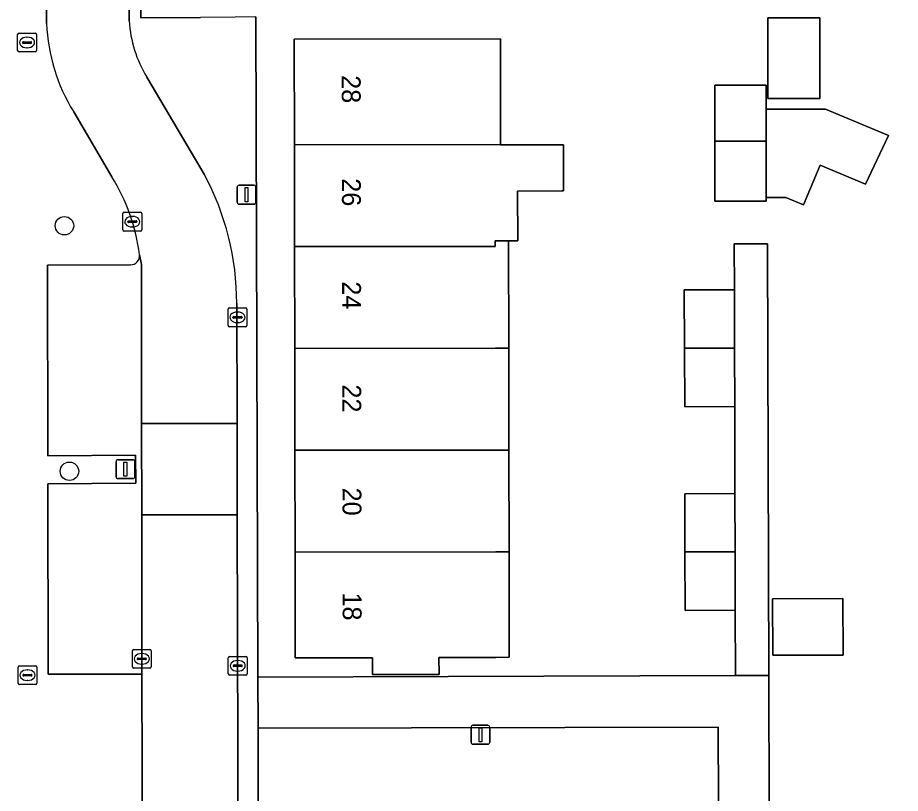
# Model space of a CAD drawing. Extents: x 160455 to 162082, y 388339 to 389736.
# Drawn here: x 160945.33 to 160992.11, y 388549.23 to 388590.36 of the extents above; entities that cross this region are included whole.
import ezdxf

# ---------------------------------------------------------------- set-up
doc = ezdxf.new("R2010")
doc.units = 0
for name, color, linetype in [('IMGEO_Boom', 7, 'Continuous'), ('IMGEO_Brandkraan', 7, 'Continuous'), ('IMGEO_Erf', 7, 'Continuous'), ('IMGEO_Groenvoorziening', 7, 'Continuous'), ('IMGEO_Kolk', 7, 'Continuous'), ('IMGEO_Lichtmast', 7, 'Continuous'), ('IMGEO_Muur', 7, 'Continuous'), ('IMGEO_Pand', 7, 'Continuous'), ('IMGEO_Pand_nummerreeks', 7, 'Continuous'), ('IMGEO_Parkeervlak_open', 7, 'Continuous'), ('IMGEO_Rijbaan_lokaal_open', 7, 'Continuous'), ('IMGEO_Voetpad_open', 7, 'Continuous')]:
    doc.layers.add(name, color=color, linetype=linetype)

msp = doc.modelspace()

# ---------------------------------------------------------------- linework, layer by layer
at = {"layer": 'IMGEO_Boom'}
for centre in [(160947.807, 388579.324), (160948.073, 388566.305)]:
    msp.add_circle(centre, 0.489, dxfattribs=at)
at = {"layer": 'IMGEO_Brandkraan'}
for p, q in [((160945.326, 388588.611), (160945.326, 388589.463)), ((160945.401, 388589.537), (160946.253, 388589.537)), ((160945.814, 388589.317), (160945.839, 388589.317)), ((160946.327, 388589.463), (160946.327, 388588.611)), ((160945.585, 388589.031), (160945.585, 388589.043)), ((160946.023, 388588.994), (160945.625, 388588.994)), ((160945.628, 388589.08), (160946.026, 388589.08)), ((160945.837, 388588.757), (160945.812, 388588.757)), ((160946.069, 388589.043), (160946.069, 388589.031)), ((160946.253, 388588.537), (160945.401, 388588.537)), ((160945.347, 388555.071), (160945.347, 388555.923)), ((160945.422, 388555.997), (160946.274, 388555.997)), ((160945.649, 388555.54), (160946.047, 388555.54)), ((160945.835, 388555.777), (160945.86, 388555.777)), ((160946.348, 388555.923), (160946.348, 388555.071)), ((160945.606, 388555.491), (160945.606, 388555.503)), ((160946.044, 388555.454), (160945.646, 388555.454)), ((160945.858, 388555.217), (160945.833, 388555.217)), ((160946.09, 388555.503), (160946.09, 388555.491)), ((160946.274, 388554.997), (160945.422, 388554.997))]:
    msp.add_line(p, q, dxfattribs=at)
for points in [[(160945.326, 388588.611), (160945.326, 388589.463)], [(160945.401, 388589.537), (160946.253, 388589.537)], [(160946.327, 388589.463), (160946.327, 388588.611)], [(160946.253, 388588.537), (160945.401, 388588.537)], [(160945.347, 388555.071), (160945.347, 388555.923)], [(160945.422, 388555.997), (160946.274, 388555.997)], [(160946.348, 388555.923), (160946.348, 388555.071)], [(160946.274, 388554.997), (160945.422, 388554.997)]]:
    msp.add_lwpolyline(points, dxfattribs=at)
for centre, radius, start, end in [((160945.403, 388589.461), 0.0765, 91.552, 178.448), ((160945.403, 388589.461), 0.0765, 91.552, 178.448), ((160946.251, 388589.461), 0.0765, 1.552, 88.448), ((160946.251, 388589.461), 0.0765, 1.552, 88.448), ((160945.625, 388589.04), 0.0403, 85.8775, 175.7526), ((160945.622, 388589.03), 0.0366, 178.938, 274.7102), ((160946.026, 388589.037), 0.043, 264.8664, 352.4533), ((160946.03, 388589.042), 0.0386, 1.7309, 96.639), ((160945.403, 388588.613), 0.0765, 181.552, 268.448), ((160945.403, 388588.613), 0.0765, 181.552, 268.448), ((160946.251, 388588.613), 0.0765, 271.552, 358.448), ((160946.251, 388588.613), 0.0765, 271.552, 358.448), ((160945.424, 388555.921), 0.0765, 91.552, 178.448), ((160945.424, 388555.921), 0.0765, 91.552, 178.448), ((160945.646, 388555.5), 0.0403, 85.8775, 175.7526), ((160946.051, 388555.502), 0.0386, 1.7309, 96.639), ((160946.272, 388555.921), 0.0765, 1.552, 88.448), ((160946.272, 388555.921), 0.0765, 1.552, 88.448), ((160945.424, 388555.073), 0.0765, 181.552, 268.448), ((160945.424, 388555.073), 0.0765, 181.552, 268.448), ((160945.643, 388555.49), 0.0366, 178.938, 274.7102), ((160946.047, 388555.497), 0.043, 264.8664, 352.4533), ((160946.272, 388555.073), 0.0765, 271.552, 358.448), ((160946.272, 388555.073), 0.0765, 271.552, 358.448)]:
    msp.add_arc(centre, radius, start, end, dxfattribs=at)
for centre, major_axis, ratio, start_param, end_param in [((160945.813, 388589.037), (-0.387, 0.002), 0.722429, 4.712389, 7.853982), ((160945.838, 388589.037), (-0.39, 0.002), 0.717154, 1.570796, 4.712389), ((160945.834, 388555.497), (-0.387, 0.002), 0.722429, 4.712389, 7.853982), ((160945.859, 388555.497), (-0.39, 0.002), 0.717154, 1.570796, 4.712389)]:
    msp.add_ellipse(centre, major_axis=major_axis, ratio=ratio, start_param=start_param, end_param=end_param, dxfattribs=at)
at = {"layer": 'IMGEO_Erf'}
for points in [[(160951.847, 388593.555), (160951.861, 388590.348), (160955.023, 388590.37)], [(160957.949, 388590.391), (160958.051, 388555.395), (160968.14, 388555.428), (160983.369, 388555.475), (160983.358, 388558.935), (160980.699, 388558.927), (160980.689, 388562.038), (160980.68, 388565.117), (160983.338, 388565.126), (160983.338, 388569.735), (160980.679, 388569.727), (160980.669, 388572.838), (160980.66, 388575.917), (160983.318, 388575.926), (160983.31, 388578.36), (160985.07, 388578.366), (160985.147, 388555.481), (160985.162, 388548.37)]]:
    msp.add_lwpolyline(points, dxfattribs=at)
for points in [[(160987.85, 388586.062), (160985.087, 388586.062), (160985.087, 388590.342), (160987.85, 388590.342)], [(160970.921, 388583.612), (160974.072, 388583.618), (160974.253, 388583.618), (160974.256, 388581.167), (160974.175, 388581.167), (160971.823, 388581.163), (160971.83, 388578.532), (160971.583, 388578.531), (160971.342, 388578.53), (160971.352, 388572.83), (160971.362, 388567.433), (160971.372, 388562.031), (160971.382, 388556.442), (160970.676, 388556.44), (160968.137, 388556.434), (160967.655, 388556.433), (160967.667, 388555.533), (160964.137, 388555.524), (160964.125, 388556.423), (160960.039, 388556.412), (160960.029, 388562.021), (160960.02, 388567.422), (160960.01, 388572.822), (160960, 388578.222), (160959.991, 388583.627), (160959.981, 388589.211), (160970.911, 388589.231)], [(160985.003, 388585.504), (160988.141, 388585.504), (160991.484, 388584.1), (160990.267, 388581.523), (160987.857, 388582.534), (160986.975, 388580.433), (160986.04, 388580.825), (160985.003, 388580.825), (160985.003, 388580.627), (160982.273, 388580.627), (160982.273, 388583.801), (160982.273, 388586.785), (160985.003, 388586.785)], [(160989.066, 388559.56), (160989.073, 388556.559), (160985.348, 388556.551), (160985.341, 388559.551)]]:
    msp.add_lwpolyline(points, close=True, dxfattribs=at)
at = {"layer": 'IMGEO_Groenvoorziening'}
msp.add_lwpolyline([(160958.098, 388540.667), (160982.501, 388540.818), (160982.455, 388552.733), (160958.068, 388552.684)], close=True, dxfattribs=at)
at = {"layer": 'IMGEO_Kolk'}
for p, q in [((160950.903, 388579.112), (160950.903, 388579.964)), ((160950.978, 388580.038), (160951.83, 388580.038)), ((160951.904, 388579.964), (160951.904, 388579.112)), ((160951.162, 388579.532), (160951.162, 388579.544)), ((160951.6, 388579.495), (160951.202, 388579.495)), ((160951.205, 388579.581), (160951.603, 388579.581)), ((160951.391, 388579.818), (160951.416, 388579.818)), ((160951.646, 388579.544), (160951.646, 388579.532)), ((160951.83, 388579.038), (160950.978, 388579.038)), ((160951.414, 388579.258), (160951.389, 388579.258)), ((160956.477, 388574.042), (160956.477, 388574.894)), ((160956.552, 388574.968), (160957.404, 388574.968)), ((160956.965, 388574.748), (160956.99, 388574.748)), ((160957.478, 388574.894), (160957.478, 388574.042)), ((160956.736, 388574.462), (160956.736, 388574.474)), ((160957.174, 388574.425), (160956.776, 388574.425)), ((160956.779, 388574.511), (160957.177, 388574.511)), ((160957.22, 388574.474), (160957.22, 388574.462)), ((160957.404, 388573.968), (160956.552, 388573.968)), ((160956.988, 388574.188), (160956.963, 388574.188)), ((160951.406, 388555.936), (160951.406, 388556.788)), ((160951.481, 388556.862), (160952.333, 388556.862)), ((160951.894, 388556.642), (160951.919, 388556.642)), ((160952.407, 388556.788), (160952.407, 388555.936)), ((160956.566, 388556.493), (160957.418, 388556.493)), ((160951.665, 388556.356), (160951.665, 388556.368)), ((160952.103, 388556.319), (160951.705, 388556.319)), ((160951.708, 388556.405), (160952.106, 388556.405)), ((160951.917, 388556.082), (160951.892, 388556.082)), ((160952.149, 388556.368), (160952.149, 388556.356)), ((160956.491, 388555.567), (160956.491, 388556.419)), ((160956.793, 388556.036), (160957.191, 388556.036)), ((160956.979, 388556.273), (160957.004, 388556.273)), ((160957.492, 388556.419), (160957.492, 388555.567)), ((160952.333, 388555.862), (160951.481, 388555.862)), ((160956.75, 388555.987), (160956.75, 388555.999)), ((160957.188, 388555.95), (160956.79, 388555.95)), ((160957.002, 388555.713), (160956.977, 388555.713)), ((160957.234, 388555.999), (160957.234, 388555.987)), ((160957.418, 388555.493), (160956.566, 388555.493))]:
    msp.add_line(p, q, dxfattribs=at)
for points in [[(160950.903, 388579.112), (160950.903, 388579.964)], [(160950.978, 388580.038), (160951.83, 388580.038)], [(160951.904, 388579.964), (160951.904, 388579.112)], [(160951.83, 388579.038), (160950.978, 388579.038)], [(160956.477, 388574.042), (160956.477, 388574.894)], [(160956.552, 388574.968), (160957.404, 388574.968)], [(160957.478, 388574.894), (160957.478, 388574.042)], [(160957.404, 388573.968), (160956.552, 388573.968)], [(160951.406, 388555.936), (160951.406, 388556.788)], [(160951.481, 388556.862), (160952.333, 388556.862)], [(160952.407, 388556.788), (160952.407, 388555.936)], [(160956.566, 388556.493), (160957.418, 388556.493)], [(160956.491, 388555.567), (160956.491, 388556.419)], [(160957.492, 388556.419), (160957.492, 388555.567)], [(160952.333, 388555.862), (160951.481, 388555.862)], [(160957.418, 388555.493), (160956.566, 388555.493)]]:
    msp.add_lwpolyline(points, dxfattribs=at)
for centre, radius, start, end in [((160950.98, 388579.962), 0.0765, 91.552, 178.448), ((160950.98, 388579.962), 0.0765, 91.552, 178.448), ((160951.828, 388579.962), 0.0765, 1.552, 88.448), ((160951.828, 388579.962), 0.0765, 1.552, 88.448), ((160951.202, 388579.541), 0.0403, 85.8775, 175.7526), ((160951.199, 388579.531), 0.0366, 178.938, 274.7102), ((160951.603, 388579.538), 0.043, 264.8664, 352.4533), ((160951.607, 388579.543), 0.0386, 1.7309, 96.639), ((160950.98, 388579.114), 0.0765, 181.552, 268.448), ((160950.98, 388579.114), 0.0765, 181.552, 268.448), ((160951.828, 388579.114), 0.0765, 271.552, 358.448), ((160951.828, 388579.114), 0.0765, 271.552, 358.448), ((160956.554, 388574.892), 0.0765, 91.552, 178.448), ((160956.554, 388574.892), 0.0765, 91.552, 178.448), ((160957.402, 388574.892), 0.0765, 1.552, 88.448), ((160957.402, 388574.892), 0.0765, 1.552, 88.448), ((160956.776, 388574.471), 0.0403, 85.8775, 175.7526), ((160956.773, 388574.461), 0.0366, 178.938, 274.7102), ((160957.177, 388574.468), 0.043, 264.8664, 352.4533), ((160957.181, 388574.473), 0.0386, 1.7309, 96.639), ((160956.554, 388574.044), 0.0765, 181.552, 268.448), ((160956.554, 388574.044), 0.0765, 181.552, 268.448), ((160957.402, 388574.044), 0.0765, 271.552, 358.448), ((160957.402, 388574.044), 0.0765, 271.552, 358.448), ((160951.483, 388556.786), 0.0765, 91.552, 178.448), ((160951.483, 388556.786), 0.0765, 91.552, 178.448), ((160952.331, 388556.786), 0.0765, 1.552, 88.448), ((160952.331, 388556.786), 0.0765, 1.552, 88.448), ((160956.568, 388556.417), 0.0765, 91.552, 178.448), ((160956.568, 388556.417), 0.0765, 91.552, 178.448), ((160957.416, 388556.417), 0.0765, 1.552, 88.448), ((160957.416, 388556.417), 0.0765, 1.552, 88.448), ((160951.705, 388556.365), 0.0403, 85.8775, 175.7526), ((160951.702, 388556.355), 0.0366, 178.938, 274.7102), ((160952.106, 388556.362), 0.043, 264.8664, 352.4533), ((160952.11, 388556.367), 0.0386, 1.7309, 96.639), ((160956.79, 388555.996), 0.0403, 85.8775, 175.7526), ((160957.195, 388555.998), 0.0386, 1.7309, 96.639), ((160951.483, 388555.938), 0.0765, 181.552, 268.448), ((160951.483, 388555.938), 0.0765, 181.552, 268.448), ((160952.331, 388555.938), 0.0765, 271.552, 358.448), ((160952.331, 388555.938), 0.0765, 271.552, 358.448), ((160956.568, 388555.569), 0.0765, 181.552, 268.448), ((160956.568, 388555.569), 0.0765, 181.552, 268.448), ((160956.787, 388555.986), 0.0366, 178.938, 274.7102), ((160957.191, 388555.993), 0.043, 264.8664, 352.4533), ((160957.416, 388555.569), 0.0765, 271.552, 358.448), ((160957.416, 388555.569), 0.0765, 271.552, 358.448)]:
    msp.add_arc(centre, radius, start, end, dxfattribs=at)
for centre, major_axis, ratio, start_param, end_param in [((160951.39, 388579.538), (-0.387, 0.002), 0.722429, 4.712389, 7.853982), ((160951.415, 388579.538), (-0.39, 0.002), 0.717154, 1.570796, 4.712389), ((160956.964, 388574.468), (-0.387, 0.002), 0.722429, 4.712389, 7.853982), ((160956.989, 388574.468), (-0.39, 0.002), 0.717154, 1.570796, 4.712389), ((160951.893, 388556.362), (-0.387, 0.002), 0.722429, 4.712389, 7.853982), ((160951.918, 388556.362), (-0.39, 0.002), 0.717154, 1.570796, 4.712389), ((160956.978, 388555.993), (-0.387, 0.002), 0.722429, 4.712389, 7.853982), ((160957.003, 388555.993), (-0.39, 0.002), 0.717154, 1.570796, 4.712389)]:
    msp.add_ellipse(centre, major_axis=major_axis, ratio=ratio, start_param=start_param, end_param=end_param, dxfattribs=at)
at = {"layer": 'IMGEO_Lichtmast'}
for p, q in [((160956.961, 388580.568), (160956.961, 388581.368)), ((160956.961, 388581.368), (160956.961, 388580.568)), ((160957.061, 388581.468), (160957.851, 388581.468)), ((160957.851, 388581.468), (160957.061, 388581.468)), ((160957.951, 388581.368), (160957.951, 388580.568)), ((160957.951, 388580.568), (160957.951, 388581.368)), ((160957.851, 388580.468), (160957.061, 388580.468)), ((160957.061, 388580.468), (160957.851, 388580.468)), ((160950.541, 388566.019), (160950.541, 388566.819)), ((160950.541, 388566.819), (160950.541, 388566.019)), ((160950.641, 388566.919), (160951.431, 388566.919)), ((160951.431, 388566.919), (160950.641, 388566.919)), ((160951.531, 388566.819), (160951.531, 388566.019)), ((160951.531, 388566.019), (160951.531, 388566.819)), ((160951.431, 388565.919), (160950.641, 388565.919)), ((160950.641, 388565.919), (160951.431, 388565.919)), ((160969.359, 388551.938), (160969.359, 388552.738)), ((160969.359, 388552.738), (160969.359, 388551.938)), ((160969.459, 388552.838), (160970.249, 388552.838)), ((160970.249, 388552.838), (160969.459, 388552.838)), ((160970.349, 388552.738), (160970.349, 388551.938)), ((160970.349, 388551.938), (160970.349, 388552.738)), ((160970.249, 388551.838), (160969.459, 388551.838)), ((160969.459, 388551.838), (160970.249, 388551.838))]:
    msp.add_line(p, q, dxfattribs=at)
for points in [[(160957.381, 388581.343), (160957.531, 388581.343), (160957.531, 388580.593), (160957.381, 388580.593), (160957.381, 388581.343)], [(160950.961, 388566.794), (160951.111, 388566.794), (160951.111, 388566.044), (160950.961, 388566.044), (160950.961, 388566.794)], [(160969.779, 388552.713), (160969.929, 388552.713), (160969.929, 388551.963), (160969.779, 388551.963), (160969.779, 388552.713)]]:
    msp.add_lwpolyline(points, dxfattribs=at)
for centre, start, end in [((160957.061, 388581.368), 90, 180), ((160957.061, 388581.368), 90, 180), ((160957.851, 388581.368), 0, 90), ((160957.851, 388581.368), 360, 90), ((160957.061, 388580.568), 180, 270), ((160957.061, 388580.568), 180, 270), ((160957.851, 388580.568), 270, 0), ((160957.851, 388580.568), 270, 0), ((160950.641, 388566.819), 90, 180), ((160950.641, 388566.819), 90, 180), ((160951.431, 388566.819), 0, 90), ((160951.431, 388566.819), 360, 90), ((160950.641, 388566.019), 180, 270), ((160950.641, 388566.019), 180, 270), ((160951.431, 388566.019), 270, 0), ((160951.431, 388566.019), 270, 0), ((160969.459, 388552.738), 90, 180), ((160969.459, 388552.738), 90, 180), ((160970.249, 388552.738), 0, 90), ((160970.249, 388552.738), 360, 90), ((160969.459, 388551.938), 180, 270), ((160969.459, 388551.938), 180, 270), ((160970.249, 388551.938), 270, 0), ((160970.249, 388551.938), 270, 0)]:
    msp.add_arc(centre, 0.1, start, end, dxfattribs=at)
at = {"layer": 'IMGEO_Muur'}
for points in [[(160983.369, 388555.475), (160968.14, 388555.428)], [(160985.147, 388555.481), (160985.162, 388548.37), (161001.342, 388548.405)]]:
    msp.add_lwpolyline(points, dxfattribs=at)
at = {"layer": 'IMGEO_Pand'}
for points in [[(160987.85, 388586.062), (160987.85, 388590.342), (160985.087, 388590.342), (160985.087, 388586.062)], [(160959.991, 388583.627), (160970.921, 388583.612), (160970.911, 388589.231), (160959.981, 388589.211)], [(160985.003, 388585.504), (160985.003, 388586.785), (160982.273, 388586.785), (160982.273, 388583.801), (160982.502, 388583.805), (160985.003, 388583.806)], [(160985.003, 388585.504), (160985.003, 388583.806), (160985.003, 388580.825), (160986.04, 388580.825), (160986.975, 388580.433), (160987.857, 388582.534), (160990.267, 388581.523), (160991.484, 388584.1), (160988.141, 388585.504)], [(160970.921, 388583.612), (160959.991, 388583.627), (160960, 388578.222), (160970.636, 388578.23), (160970.636, 388578.528), (160971.342, 388578.53), (160971.583, 388578.531), (160971.83, 388578.532), (160971.823, 388581.163), (160974.175, 388581.167), (160974.256, 388581.167), (160974.253, 388583.618), (160974.072, 388583.618)], [(160985.003, 388583.806), (160982.502, 388583.805), (160982.273, 388583.801), (160982.273, 388580.627), (160985.003, 388580.627), (160985.003, 388580.825)], [(160971.342, 388578.53), (160970.636, 388578.528), (160970.636, 388578.23), (160960, 388578.222), (160960.01, 388572.822), (160970.646, 388572.83), (160971.352, 388572.83)], [(160983.328, 388572.84), (160983.318, 388575.926), (160980.66, 388575.917), (160980.669, 388572.838)], [(160971.352, 388572.83), (160970.646, 388572.83), (160960.01, 388572.822), (160960.02, 388567.422), (160968.434, 388567.428), (160970.656, 388567.432), (160971.362, 388567.433)], [(160983.328, 388572.84), (160980.669, 388572.838), (160980.679, 388569.727), (160983.338, 388569.735)], [(160971.362, 388567.433), (160970.656, 388567.432), (160968.434, 388567.428), (160960.02, 388567.422), (160960.029, 388562.021), (160970.666, 388562.03), (160971.372, 388562.031)], [(160983.348, 388562.041), (160983.338, 388565.126), (160980.68, 388565.117), (160980.689, 388562.038)], [(160971.372, 388562.031), (160970.666, 388562.03), (160960.029, 388562.021), (160960.039, 388556.412), (160964.125, 388556.423), (160964.137, 388555.524), (160967.667, 388555.533), (160967.655, 388556.433), (160968.137, 388556.434), (160970.676, 388556.44), (160971.382, 388556.442)], [(160983.348, 388562.041), (160980.689, 388562.038), (160980.699, 388558.927), (160983.358, 388558.935)], [(160985.341, 388559.551), (160985.348, 388556.551), (160989.073, 388556.559), (160989.066, 388559.56)]]:
    msp.add_lwpolyline(points, close=True, dxfattribs=at)
at = {"layer": 'IMGEO_Parkeervlak_open'}
msp.add_lwpolyline([(160951.302, 388577.252), (160946.905, 388577.232), (160946.922, 388567.128), (160951.574, 388567.157), (160951.585, 388565.673), (160946.926, 388565.636), (160946.95, 388555.547), (160951.914, 388555.541), (160951.904, 388563.991), (160951.897, 388568.831), (160951.887, 388577.271), (160951.791, 388577.788)], dxfattribs=at)
msp.add_arc((160951.309, 388577.737), 0.485, 269.1937, 6.057, dxfattribs=at)
at = {"layer": 'IMGEO_Rijbaan_lokaal_open'}
for points in [[(160951.224, 388593.835), (160951.194, 388615.777), (160946.624, 388615.788), (160946.807, 388609.308), (160946.861, 388593.811), (160946.863, 388590.044)], [(160951.241, 388590.183), (160951.242, 388590.402), (160951.224, 388593.835)], [(160955.213, 388582.054), (160952.174, 388587.207)], [(160948.296, 388585.366), (160950.322, 388581.918)], [(160951.791, 388577.788), (160951.887, 388577.271), (160951.897, 388568.831), (160956.954, 388568.844), (160956.936, 388575.196)]]:
    msp.add_lwpolyline(points, dxfattribs=at)
for points in [[(160951.897, 388568.831), (160951.904, 388563.991), (160956.967, 388564.004), (160956.954, 388568.844)], [(160951.914, 388537.902), (160951.933, 388529.556), (160957.055, 388529.559), (160957.054, 388532.505), (160956.967, 388564.004), (160951.904, 388563.991), (160951.914, 388555.541), (160951.929, 388550.409), (160951.946, 388543.023)]]:
    msp.add_lwpolyline(points, close=True, dxfattribs=at)
for centre, radius, start, end in [((160957.555, 388590.528), 6.323, 183.1288, 211.6844), ((160956.377, 388590.4), 9.521, 182.1429, 211.9196), ((160941.357, 388576.403), 10.525, 7.561, 31.5989), ((160942.632, 388575.248), 14.304, 359.7926, 28.4136)]:
    msp.add_arc(centre, radius, start, end, dxfattribs=at)
at = {"layer": 'IMGEO_Voetpad_open'}
for points in [[(160946.863, 388590.044), (160946.861, 388593.811), (160946.807, 388609.308), (160946.624, 388615.788), (160946.592, 388616.937)], [(160958.183, 388500), (160958.111, 388537.937), (160958.098, 388540.667), (160958.068, 388552.684), (160958.051, 388555.395), (160957.949, 388590.391), (160956.859, 388590.383), (160955.023, 388590.37), (160951.861, 388590.348), (160951.847, 388593.555), (160951.827, 388605.484), (160951.807, 388617.13)], [(160951.193, 388616.365), (160951.194, 388615.777), (160951.224, 388593.835), (160951.242, 388590.402), (160951.241, 388590.183)], [(160952.174, 388587.207), (160955.213, 388582.054)], [(160950.322, 388581.918), (160948.296, 388585.366)], [(160951.946, 388543.023), (160951.929, 388550.409), (160951.914, 388555.541), (160946.95, 388555.547), (160946.926, 388565.636), (160951.585, 388565.673), (160951.574, 388567.157), (160946.922, 388567.128), (160946.905, 388577.232), (160951.302, 388577.252)], [(160956.936, 388575.196), (160956.954, 388568.844), (160956.967, 388564.004), (160957.054, 388532.505), (160957.055, 388529.559), (160957.055, 388524.739), (160957.057, 388516.024), (160957.083, 388505.799)]]:
    msp.add_lwpolyline(points, dxfattribs=at)
for points in [[(160985.07, 388578.366), (160983.31, 388578.36), (160983.318, 388575.926), (160983.328, 388572.84), (160983.338, 388569.735), (160983.338, 388565.126), (160983.348, 388562.041), (160983.358, 388558.935), (160983.369, 388555.475), (160985.147, 388555.481)], [(160985.147, 388555.481), (160983.369, 388555.475), (160968.14, 388555.428), (160958.051, 388555.395), (160958.068, 388552.684), (160982.455, 388552.733), (160982.501, 388540.818), (160958.098, 388540.667), (160958.111, 388537.937), (160968.208, 388537.986), (160983.437, 388538.059), (160985.186, 388538.067), (160985.179, 388541.624), (160985.172, 388546.374), (160985.162, 388548.37)]]:
    msp.add_lwpolyline(points, close=True, dxfattribs=at)
for centre, radius, start, end in [((160957.555, 388590.528), 6.323, 183.1288, 211.6844), ((160956.377, 388590.4), 9.521, 182.1429, 211.9196), ((160941.357, 388576.403), 10.525, 7.561, 31.5989), ((160942.632, 388575.248), 14.304, 359.7926, 28.4136), ((160951.309, 388577.737), 0.485, 269.1937, 6.057)]:
    msp.add_arc(centre, radius, start, end, dxfattribs=at)

# ---------------------------------------------------------------- texts
at = {"layer": 'IMGEO_Pand_nummerreeks'}
for s, rotation, p in [('28', 270.1013, (160962.504, 388587.305)), ('26', 270.1029, (160962.514, 388581.841)), ('24', 270.1029, (160962.524, 388576.375)), ('22', 270.1029, (160962.534, 388570.911)), ('20', 270.1029, (160962.543, 388565.439)), ('18', 270.1029, (160962.553, 388559.881))]:
    msp.add_text(s, height=1, rotation=rotation, dxfattribs=at).set_placement(p)

doc.saveas('drawing.dxf')
